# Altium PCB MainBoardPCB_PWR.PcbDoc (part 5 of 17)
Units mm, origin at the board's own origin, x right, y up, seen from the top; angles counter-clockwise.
Board outline 333.63 x 349.38 mm, 16 copper layers (L1, L2 (GND), L3 (Sign), L4 (GND), L5 (Sign), L6 (PWR/GND), L7(PWR/GND), L8 (PWR/GND), L9 (PWR/GND), L10 (PWR/GND), L11 (PWR/GND), L12 (Sign), L13 (GND), L14 (Sign), L15 (GND), L16), stack 2.503 mm thick; 2187 components, 1615 nets, 7987 pads, 1695 vias.
Unrouted connection lines stored in the file: 4757.
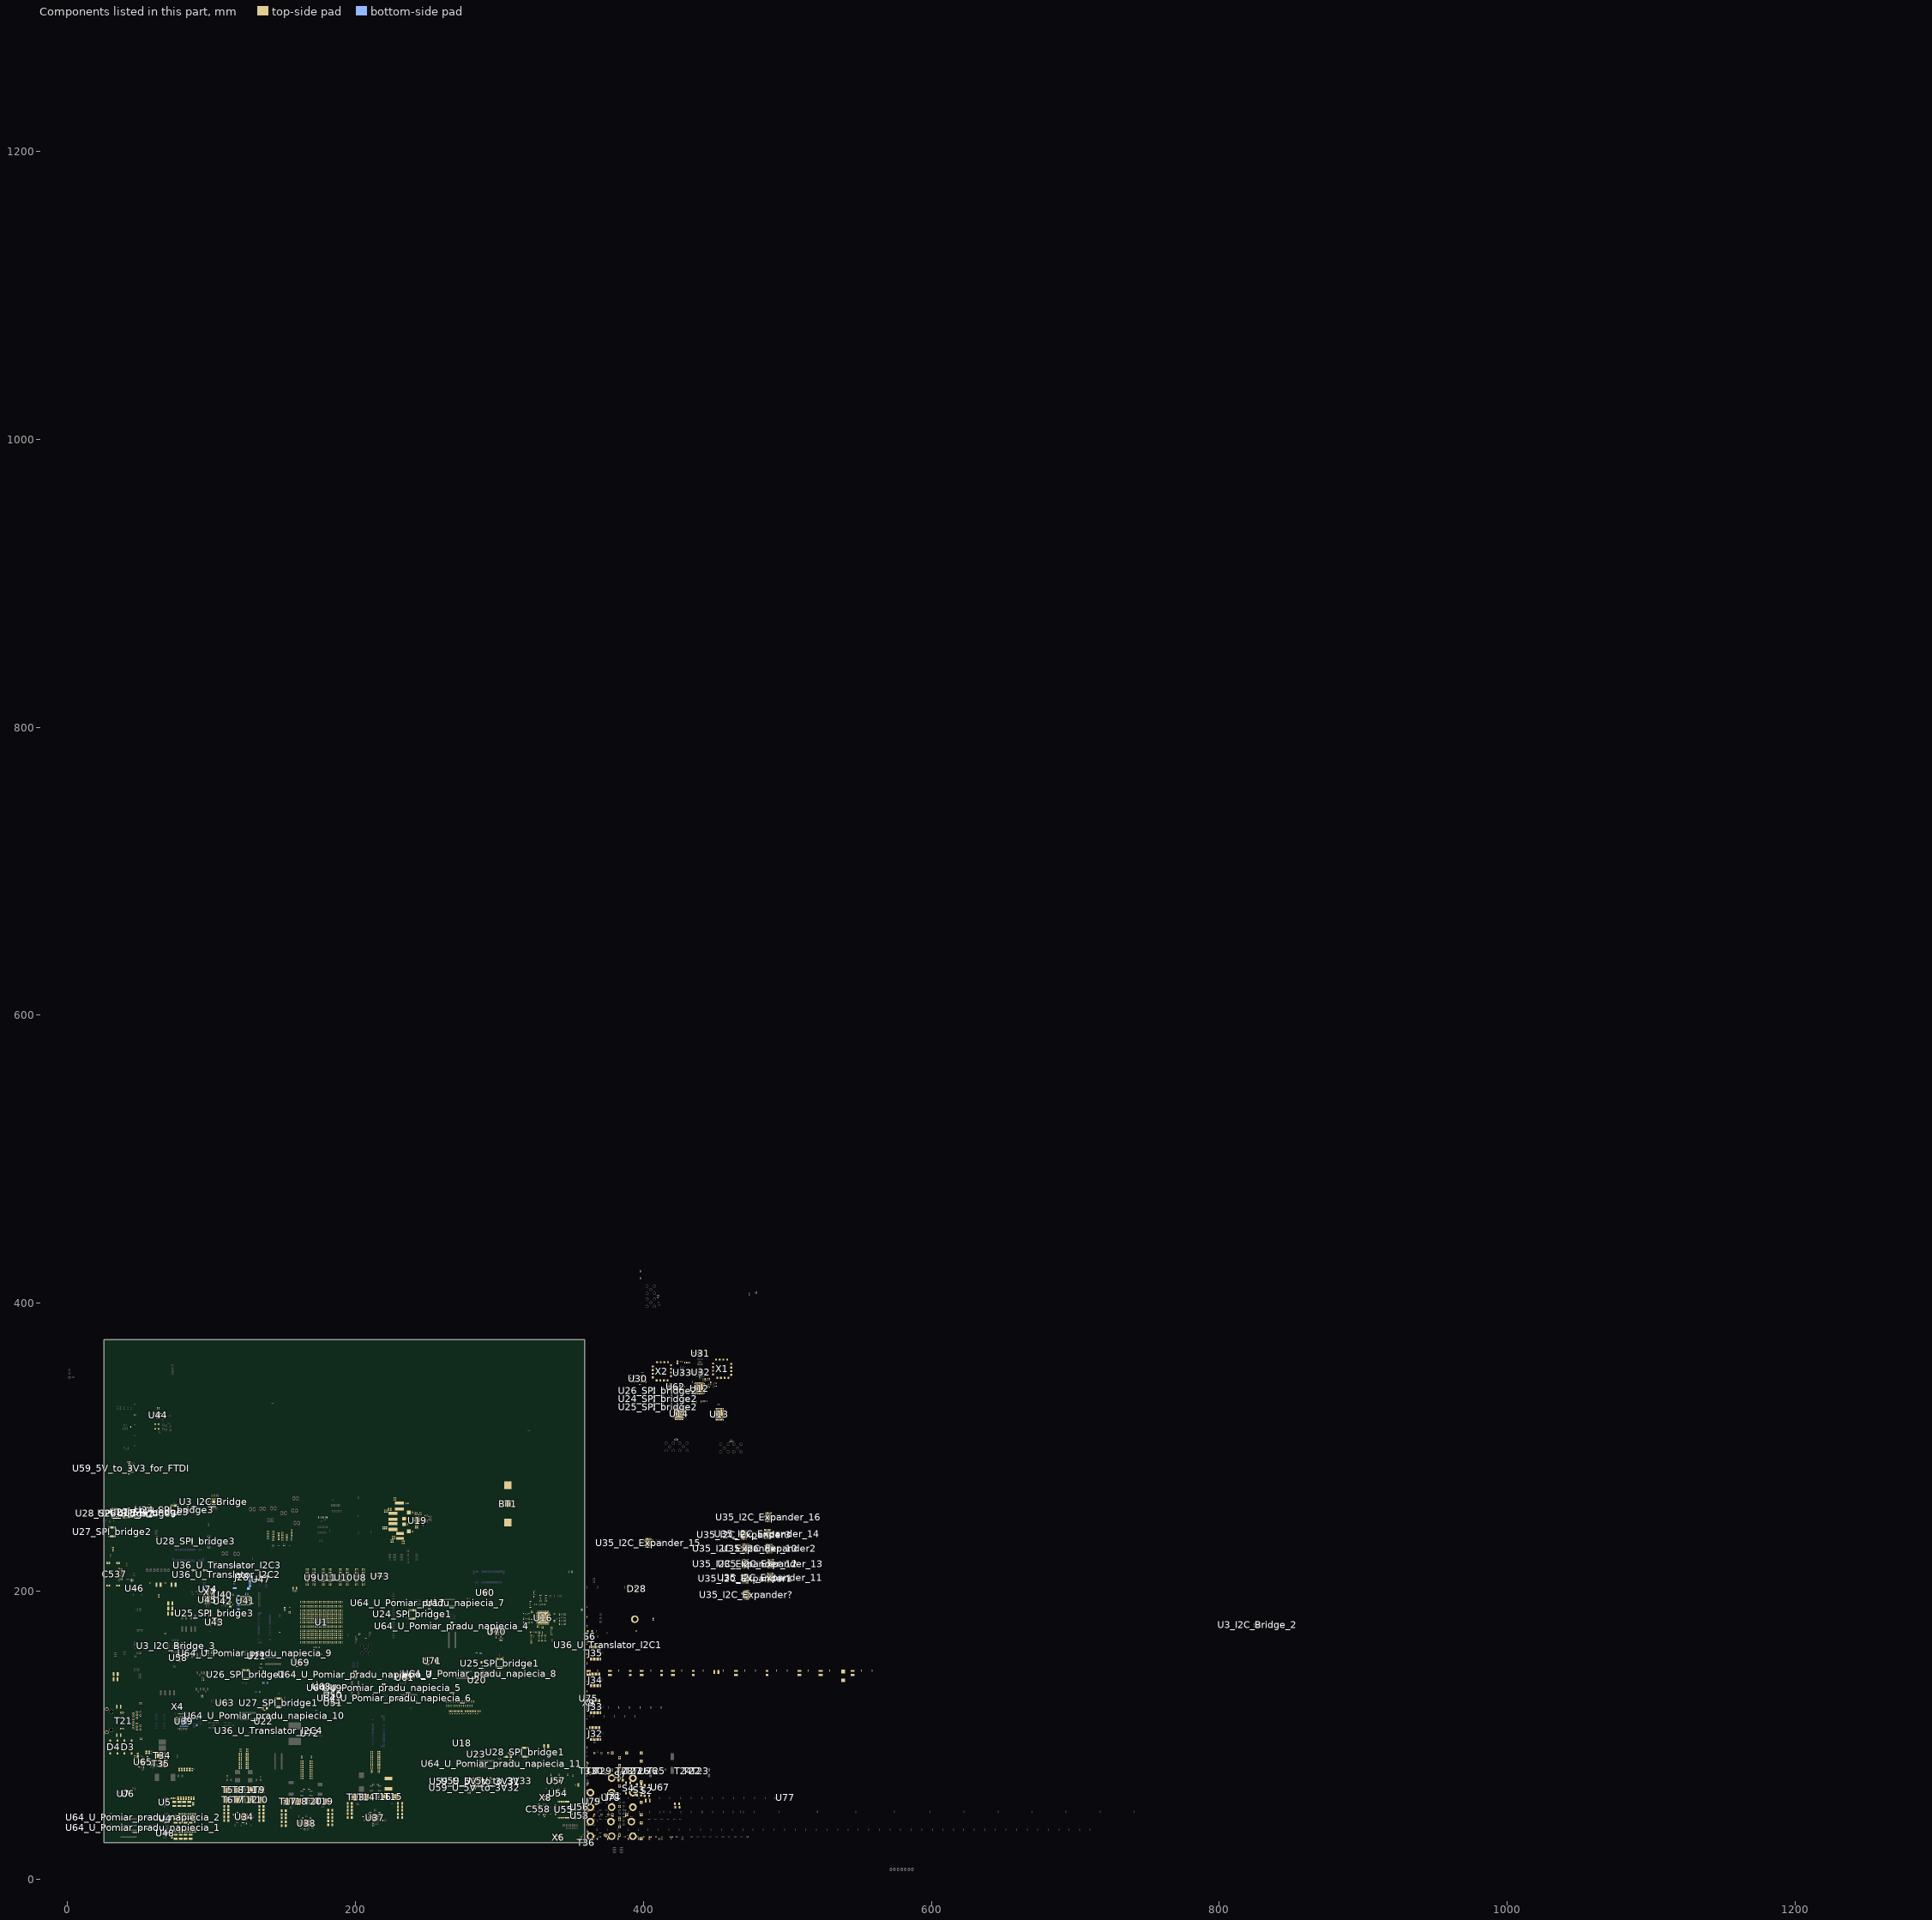
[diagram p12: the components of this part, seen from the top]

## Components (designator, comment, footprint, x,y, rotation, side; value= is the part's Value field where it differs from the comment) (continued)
T21 "7499511440" 7499511440 36.068,109.982 r90 bottom
T22 "IRLML6401TRPBF" IRLML6401PbF 433.807,75.082 r0 top
T23 "IRLML6401TRPBF" IRLML6401PbF 439.661,75.082 r0 top
T24 "SI2342DS-T1-GE3" SI2342DS-T1-GE3 427.952,75.184 r0 top
T25 "SI2342DS-T1-GE3" SI2342DS-T1-GE3 409.27,75.184 r0 top
T26 "SI2342DS-T1-GE3" SI2342DS-T1-GE3 398.882,75.184 r0 top
T27 "IRLML6401TRPBF" IRLML6401PbF 393.027,75.082 r0 top
T28 "SI2342DS-T1-GE3" SI2342DS-T1-GE3 387.172,75.184 r0 top
T29 "SI2342DS-T1-GE3" SI2342DS-T1-GE3 372.224,75.184 r0 top
T30 "IRLML6401TRPBF" IRLML6401PbF 366.37,75.082 r0 top
T31 "SI2342DS-T1-GE3" SI2342DS-T1-GE3 361.899,75.184 r0 top
T34 "RJK0651DPB-00#J5" RJK0651DPB 64.98,85.852 r180 top
T35 "SIJ482DP-T1-GE3" SiJ482DP 65.046,80.055 r0 top
T36 "SI2342DS-T1-GE3" SI2342DS-T1-GE3 360.505,25.232 r0 top
TP1_I2C_Bridge "TestPoint" TestPoint 766.635,73.393 r90 top (schematic designator TP1)
TP1_I2C_Bridge_2 "TestPoint" TestPoint 801.167,176.378 r90 top (schematic designator TP1)
TP1_I2C_Bridge_3 "TestPoint" TestPoint 775.271,83.629 r90 top (schematic designator TP1)
TP2_I2C_Bridge "TestPoint" TestPoint 743.534,73.393 r90 top (schematic designator TP2)
TP2_I2C_Bridge_2 "TestPoint" TestPoint 776.046,176.378 r90 top (schematic designator TP2)
TP2_I2C_Bridge_3 "TestPoint" TestPoint 751.662,83.629 r90 top (schematic designator TP2)
TP3_I2C_Bridge "TestPoint" TestPoint 720.42,73.393 r90 top (schematic designator TP3)
TP3_I2C_Bridge_2 "TestPoint" TestPoint 750.9,176.378 r90 top (schematic designator TP3)
TP3_I2C_Bridge_3 "TestPoint" TestPoint 728.04,83.629 r90 top (schematic designator TP3)
TP4_I2C_Bridge "TestPoint" TestPoint 697.319,73.393 r90 top (schematic designator TP4)
TP4_I2C_Bridge_2 "TestPoint" TestPoint 725.754,176.378 r90 top (schematic designator TP4)
TP4_I2C_Bridge_3 "TestPoint" TestPoint 704.418,83.629 r90 top (schematic designator TP4)
TP5_I2C_Bridge "TestPoint" TestPoint 674.205,73.393 r90 top (schematic designator TP5)
TP5_I2C_Bridge_2 "TestPoint" TestPoint 700.608,176.378 r90 top (schematic designator TP5)
TP5_I2C_Bridge_3 "TestPoint" TestPoint 680.809,83.629 r90 top (schematic designator TP5)
TP6_I2C_Bridge "TestPoint" TestPoint 651.104,73.393 r90 top (schematic designator TP6)
TP6_I2C_Bridge_2 "TestPoint" TestPoint 675.488,176.378 r90 top (schematic designator TP6)
TP6_I2C_Bridge_3 "TestPoint" TestPoint 657.187,83.629 r90 top (schematic designator TP6)
TP7_I2C_Bridge "TestPoint" TestPoint 484.518,73.393 r90 top (schematic designator TP7)
TP7_I2C_Bridge_2 "TestPoint" TestPoint 494.69,176.378 r90 top (schematic designator TP7)
TP7_I2C_Bridge_3 "TestPoint" TestPoint 487.058,83.629 r90 top (schematic designator TP7)
TP8_I2C_Bridge "TestPoint" TestPoint 627.99,73.393 r90 top (schematic designator TP8)
TP8_I2C_Bridge_2 "TestPoint" TestPoint 650.342,176.378 r90 top (schematic designator TP8)
TP8_I2C_Bridge_3 "TestPoint" TestPoint 633.578,83.629 r90 top (schematic designator TP8)
TP9_I2C_Bridge "TestPoint" TestPoint 604.888,73.393 r90 top (schematic designator TP9)
TP9_I2C_Bridge_2 "TestPoint" TestPoint 625.196,176.378 r90 top (schematic designator TP9)
TP9_I2C_Bridge_3 "TestPoint" TestPoint 609.956,83.629 r90 top (schematic designator TP9)
TP10_I2C_Bridge "TestPoint" TestPoint 580.504,73.393 r90 top (schematic designator TP10)
TP10_I2C_Bridge_2 "TestPoint" TestPoint 598.805,176.378 r90 top (schematic designator TP10)
TP10_I2C_Bridge_3 "TestPoint" TestPoint 585.076,83.629 r90 top (schematic designator TP10)
TP11_I2C_Bridge "TestPoint" TestPoint 556.387,73.393 r90 top (schematic designator TP11)
TP11_I2C_Bridge_2 "TestPoint" TestPoint 572.643,176.378 r90 top (schematic designator TP11)
TP11_I2C_Bridge_3 "TestPoint" TestPoint 560.438,83.629 r90 top (schematic designator TP11)
TP12_I2C_Bridge "TestPoint" TestPoint 532.003,73.393 r90 top (schematic designator TP12)
TP12_I2C_Bridge_2 "TestPoint" TestPoint 546.227,176.378 r90 top (schematic designator TP12)
TP12_I2C_Bridge_3 "TestPoint" TestPoint 535.559,83.629 r90 top (schematic designator TP12)
TP13_I2C_Bridge "TestPoint" TestPoint 507.632,73.393 r90 top (schematic designator TP13)
TP13_I2C_Bridge_2 "TestPoint" TestPoint 519.811,176.378 r90 top (schematic designator TP13)
TP13_I2C_Bridge_3 "TestPoint" TestPoint 510.667,83.629 r90 top (schematic designator TP13)
TP14_I2C_Bridge "TestPoint" TestPoint 460.146,73.393 r90 top (schematic designator TP14)
TP14_I2C_Bridge_2 "TestPoint" TestPoint 468.274,176.378 r90 top (schematic designator TP14)
TP14_I2C_Bridge_3 "TestPoint" TestPoint 462.166,83.629 r90 top (schematic designator TP14)
TP15_I2C_Bridge "TestPoint" TestPoint 534.889,26.273 r90 top (schematic designator TP15)
TP15_I2C_Bridge_2 "TestPoint" TestPoint 441.858,176.378 r90 top (schematic designator TP15)
TP15_I2C_Bridge_3 "TestPoint" TestPoint 437.286,83.629 r90 top (schematic designator TP15)
TP16_I2C_Bridge "TestPoint" TestPoint 531.012,27.724 r90 top (schematic designator TP16)
TP16_I2C_Bridge_2 "TestPoint" TestPoint 415.442,176.378 r90 top (schematic designator TP16)
TP16_I2C_Bridge_3 "TestPoint" TestPoint 522.58,112.344 r90 top (schematic designator TP16)
TP17_I2C_Bridge "TestPoint" TestPoint 524.713,29.273 r90 top (schematic designator TP17)
TP17_I2C_Bridge_2 "TestPoint" TestPoint 389.052,176.378 r90 top (schematic designator TP17)
TP17_I2C_Bridge_3 "TestPoint" TestPoint 499.605,110.401 r90 top (schematic designator TP17)
TP18_I2C_Bridge "TestPoint" TestPoint 516.382,26.772 r90 top (schematic designator TP18)
TP18_I2C_Bridge_2 "TestPoint" TestPoint 362.636,176.378 r90 top (schematic designator TP18)
TP18_I2C_Bridge_3 "TestPoint" TestPoint 506.4,116.599 r90 top (schematic designator TP18)
TP19 "TestPoint" TestPoint 371.297,22.606 r0 top
TP20 "TestPoint" TestPoint 365.925,19.431 r0 top
TP21 "TestPoint" TestPoint 544.187,14.173 r0 top
TP22 "TestPoint" TestPoint 536.821,14.173 r0 top
TP23 "TestPoint" TestPoint 529.455,14.173 r0 top
TP24 "TestPoint" TestPoint 522.089,14.173 r0 top
TP25 "TestPoint" TestPoint 514.723,14.173 r0 top
TP26 "TestPoint" TestPoint 507.357,14.173 r0 top
TP27 "TestPoint" TestPoint 500.004,14.173 r0 top
TP28 "TestPoint" TestPoint 492.638,14.173 r0 top
TP29 "TestPoint" TestPoint 485.272,14.173 r0 top
TP30 "TestPoint" TestPoint 477.906,14.173 r0 top
TP31 "TestPoint" TestPoint 470.984,14.173 r0 top
TP32 "TestPoint" TestPoint 463.618,14.173 r0 top
TP33 "TestPoint" TestPoint 456.252,14.173 r0 top
TP34 "TestPoint" TestPoint 448.886,14.173 r0 top
TP35 "TestPoint" TestPoint 441.52,14.173 r0 top
TP36 "TestPoint" TestPoint 434.154,14.173 r0 top
TP37 "TestPoint" TestPoint 426.788,14.173 r0 top
TP38 "TestPoint" TestPoint 419.435,14.173 r0 top
TP39 "TestPoint" TestPoint 412.069,14.173 r0 top
TP40 "TestPoint" TestPoint 404.703,14.173 r0 top
TP41 "TestPoint" TestPoint 397.769,14.173 r0 top
TP42 "TestPoint" TestPoint 506.882,27.546 r0 top
TP43 "TestPoint" TestPoint 528.795,18.11 r0 top
TP44 "TestPoint" TestPoint 521.429,18.11 r0 top
TP45 "TestPoint" TestPoint 514.063,18.11 r0 top
TP46 "TestPoint" TestPoint 506.697,18.11 r0 top
TP47 "TestPoint" TestPoint 499.331,18.11 r0 top
TP48 "TestPoint" TestPoint 491.965,18.11 r0 top
TP49 "TestPoint" TestPoint 484.599,18.11 r0 top
TP50_SPI_bridge1 "TestPoint" TestPoint 510.172,93.866 r90 top (schematic designator TP50)
TP50_SPI_bridge2 "TestPoint" TestPoint 588.645,186.614 r90 top (schematic designator TP50)
TP50_SPI_bridge3 "TestPoint" TestPoint 513.207,104.102 r90 top (schematic designator TP50)
TP51_SPI_bridge1 "TestPoint" TestPoint 485.788,93.866 r90 top (schematic designator TP51)
TP51_SPI_bridge2 "TestPoint" TestPoint 563.753,186.614 r90 top (schematic designator TP51)
TP51_SPI_bridge3 "TestPoint" TestPoint 488.328,104.102 r90 top (schematic designator TP51)
TP52_SPI_bridge1 "TestPoint" TestPoint 461.162,93.866 r90 top (schematic designator TP52)
TP52_SPI_bridge2 "TestPoint" TestPoint 538.607,186.614 r90 top (schematic designator TP52)
TP52_SPI_bridge3 "TestPoint" TestPoint 463.182,104.102 r90 top (schematic designator TP52)
TP53_SPI_bridge1 "TestPoint" TestPoint 436.524,93.866 r90 top (schematic designator TP53)
TP53_SPI_bridge2 "TestPoint" TestPoint 513.461,186.614 r90 top (schematic designator TP53)
TP53_SPI_bridge3 "TestPoint" TestPoint 438.048,104.102 r90 top (schematic designator TP53)
TP54_SPI_bridge1 "TestPoint" TestPoint 411.899,93.866 r90 top (schematic designator TP54)
TP54_SPI_bridge2 "TestPoint" TestPoint 488.34,186.614 r90 top (schematic designator TP54)
TP54_SPI_bridge3 "TestPoint" TestPoint 412.915,104.102 r90 top (schematic designator TP54)
TP55_SPI_bridge1 "TestPoint" TestPoint 387.261,93.866 r90 top (schematic designator TP55)
TP55_SPI_bridge2 "TestPoint" TestPoint 463.194,186.614 r90 top (schematic designator TP55)
TP55_SPI_bridge3 "TestPoint" TestPoint 387.769,104.102 r90 top (schematic designator TP55)
TP56_SPI_bridge1 "TestPoint" TestPoint 362.636,93.866 r90 top (schematic designator TP56)
TP56_SPI_bridge2 "TestPoint" TestPoint 438.048,186.614 r90 top (schematic designator TP56)
TP56_SPI_bridge3 "TestPoint" TestPoint 365.484,103.796 r90 top (schematic designator TP56)
TP57_SPI_bridge1 "TestPoint" TestPoint 411.988,95.25 r90 top (schematic designator TP57)
TP57_SPI_bridge2 "TestPoint" TestPoint 412.928,186.614 r90 top (schematic designator TP57)
TP57_SPI_bridge3 "TestPoint" TestPoint 413.004,105.664 r90 top (schematic designator TP57)
TP58_SPI_bridge1 "TestPoint" TestPoint 387.35,95.25 r90 top (schematic designator TP58)
TP58_SPI_bridge2 "TestPoint" TestPoint 387.782,186.614 r90 top (schematic designator TP58)
TP58_SPI_bridge3 "TestPoint" TestPoint 387.858,105.664 r90 top (schematic designator TP58)
TP59_SPI_bridge1 "TestPoint" TestPoint 362.712,95.25 r90 top (schematic designator TP59)
TP59_SPI_bridge2 "TestPoint" TestPoint 362.636,186.614 r90 top (schematic designator TP59)
TP59_SPI_bridge3 "TestPoint" TestPoint 362.712,105.664 r90 top (schematic designator TP59)
TP60_U_Translator_I2C1 "TestPoint" TestPoint 395.91,196.85 r90 top (schematic designator TP60)
TP60_U_Translator_I2C2 "TestPoint" TestPoint 396.405,114.338 r90 top (schematic designator TP60)
TP60_U_Translator_I2C3 "TestPoint" TestPoint 1269.987,1269.987 r0 top (schematic designator TP60)
TP60_U_Translator_I2C4 "TestPoint" TestPoint 1269.987,1269.987 r0 top (schematic designator TP60)
TP61_U_Translator_I2C1 "TestPoint" TestPoint 362.636,196.85 r90 top (schematic designator TP61)
TP61_U_Translator_I2C2 "TestPoint" TestPoint 362.636,114.338 r90 top (schematic designator TP61)
TP61_U_Translator_I2C3 "TestPoint" TestPoint 1269.987,1269.987 r0 top (schematic designator TP61)
TP61_U_Translator_I2C4 "TestPoint" TestPoint 1269.987,1269.987 r0 top (schematic designator TP61)
TP62 "TestPoint" TestPoint 553.733,37.998 r0 top
TP63 "TestPoint" TestPoint 546.367,37.998 r0 top
TP64 "TestPoint" TestPoint 539.001,37.998 r0 top
TP65 "TestPoint" TestPoint 531.635,37.998 r0 top
TP66 "TestPoint" TestPoint 524.281,37.998 r0 top
TP67 "TestPoint" TestPoint 516.915,37.998 r0 top
TP68 "TestPoint" TestPoint 509.549,37.998 r0 top
TP69 "TestPoint" TestPoint 502.183,37.998 r0 top
TP70 "TestPoint" TestPoint 494.817,37.998 r0 top
TP71 "TestPoint" TestPoint 487.896,37.998 r0 top
TP72 "TestPoint" TestPoint 480.53,37.998 r0 top
TP73 "TestPoint" TestPoint 473.164,37.998 r0 top
TP74 "TestPoint" TestPoint 465.798,37.998 r0 top
TP75 "TestPoint" TestPoint 458.432,29.273 r0 top
TP76 "TestPoint" TestPoint 451.066,29.273 r0 top
TP77 "TestPoint" TestPoint 443.713,29.273 r0 top
TP78 "TestPoint" TestPoint 436.347,29.273 r0 top
TP79 "TestPoint" TestPoint 428.981,29.273 r0 top
TP80 "TestPoint" TestPoint 421.615,29.273 r0 top
TP81 "TestPoint" TestPoint 414.693,29.273 r0 top
TP82 "TestPoint" TestPoint 407.327,29.273 r0 top
TP83 "TestPoint" TestPoint 399.961,29.273 r0 top
TP84 "TestPoint" TestPoint 392.595,29.273 r0 top
TP85 "TestPoint" TestPoint 385.229,29.273 r0 top
TP86 "TestPoint" TestPoint 377.863,29.273 r0 top
TP87 "TestPoint" TestPoint 370.497,29.273 r0 top
TP88 "TestPoint" TestPoint 363.131,29.273 r0 top
TP91 "TestPoint" TestPoint 498.515,27.445 r0 top
TP92 "TestPoint" TestPoint 491.149,27.445 r0 top
U1 "FBVB900" "FBVB900 XX" 176.427,178.427 r90 top locked
U3_I2C_Bridge "TCA9548" TCA9548 101.6,262.001 r90 top (schematic designator U3)
U3_I2C_Bridge_2 "TCA9548" TCA9548 826.389,176.581 r90 top (schematic designator U3)
U3_I2C_Bridge_3 "TCA9548" TCA9548 75.299,161.955 r90 top (schematic designator U3)
U4 "TPS2121RUXT" TPS212x 67.81,42 r180 top
U5 "TPS2121RUXT" TPS212x 67.629,53.445 r180 top
U6 "FPF2895CUCX" FPF2895C-D 41.961,59.258 r0 top
U7 "FPF2895CUCX" FPF2895C-D 38.684,59.233 r0 top
U8 "MT40A512M16JY" MT40A512M16JY 203.187,209.448 r180 top locked
U9 "MT40A512M16JY" MT40A512M16JY 168.806,209.448 r180 top locked
U10 "MT40A512M16JY" MT40A512M16JY 191.727,209.448 r180 top locked
U11 "MT40A512M16JY" MT40A512M16JY 180.266,209.448 r180 top locked
U12 "LTC6952" LTC6952 438.868,340.842 r0 top
U13 "LTC6952" LTC6952 452.78,322.838 r0 top
U14 "LTC6952" LTC6952 424.713,323.088 r0 top
U15 "SN74AXC4T774PWR" SN74AXC4T774PWR 40.825,254.381 r90 top
U16 "LMK05028" LMK05028 330.203,181.514 r90 top
U17 "FPF2895CUCX" FPF2895C-D 255.855,191.833 r0 top
U18 "FPF2895CUCX" FPF2895C-D 274.044,94.567 r0 top
U19 "LT3504EUFD#PBF" LT3504 242.974,249.058 r0 top
U20 "FPF2895CUCX" FPF2895C-D 284.534,138.207 r270 top
U21 "FPF2895CUCX" FPF2895C-D 131.372,155.013 r270 top
U22 "FPF2895CUCX" FPF2895C-D 136.183,109.693 r90 top
U23 "FPF2895CUCX" FPF2895C-D 283.885,86.756 r0 top
U24_SPI_bridge1 "SN74AXC4T774PWR" SN74AXC4T774PWR 239.507,183.991 r270 top (schematic designator U24)
U24_SPI_bridge2 "SN74AXC4T774PWR" SN74AXC4T774PWR 410.235,333.565 r0 bottom (schematic designator U24)
U24_SPI_bridge3 "SN74AXC4T774PWR" SN74AXC4T774PWR 74.295,256.413 r90 top (schematic designator U24)
U25_SPI_bridge1 "SN74AXC4T774PWR" SN74AXC4T774PWR 300.217,149.945 r90 top (schematic designator U25)
U25_SPI_bridge2 "SN74AXC4T774PWR" SN74AXC4T774PWR 410.235,327.914 r0 bottom (schematic designator U25)
U25_SPI_bridge3 "SN74AXC4T774PWR" SN74AXC4T774PWR 101.854,184.658 r180 top (schematic designator U25)
U26_SPI_bridge1 "SN74AXC4T774PWR" SN74AXC4T774PWR 123.922,142.113 r270 top (schematic designator U26)
U26_SPI_bridge2 "SN74AXC4T774PWR" SN74AXC4T774PWR 410.235,339.217 r0 bottom (schematic designator U26)
U26_SPI_bridge3 "SN74AXC4T774PWR" SN74AXC4T774PWR 48.514,254.127 r90 top (schematic designator U26)
U27_SPI_bridge1 "SN74AXC4T774PWR" SN74AXC4T774PWR 146.685,122.555 r90 top (schematic designator U27)
U27_SPI_bridge2 "SN74AXC4T774PWR" SN74AXC4T774PWR 30.872,241.3 r90 top (schematic designator U27)
U27_SPI_bridge3 "SN74AXC4T774PWR" SN74AXC4T774PWR 56.896,254.889 r90 top (schematic designator U27)
U28_SPI_bridge1 "SN74AXC4T774PWR" SN74AXC4T774PWR 317.703,88.138 r270 top (schematic designator U28)
U28_SPI_bridge2 "SN74AXC4T774PWR" SN74AXC4T774PWR 33.147,254.127 r90 top (schematic designator U28)
U28_SPI_bridge3 "SN74AXC4T774PWR" SN74AXC4T774PWR 89.154,234.823 r180 top (schematic designator U28)
U30 "DAC1220" DAC1220 396.138,347.599 r0 top
U31 "SI53323-B-GM" SI53323-B-GM 439.675,365.129 r270 top
U32 "SI53323-B-GM" SI53323-B-GM 439.786,351.917 r270 top
U33 "CDCM1802RGTT" CDCM1802RGTT 427.002,351.786 r0 top
U34 "ADP1850ACPZ-R7" ADP1850 122.727,43.156 r90 top
U35_I2C_Expander1 "MCP23017-E/ML" QFN-ML28_N 470.886,208.717 r90 top (schematic designator U35)
U35_I2C_Expander2 "MCP23017-E/ML" QFN-ML28_N 487.165,229.565 r90 top (schematic designator U35)
U35_I2C_Expander3 "MCP23017-E/ML" QFN-ML28_N 469.845,239.27 r90 top (schematic designator U35)
U35_I2C_Expander? "MCP23017-E/ML" QFN-ML28_N 471.545,197.546 r90 top (schematic designator U35)
U35_I2C_Expander_10 "MCP23017-E/ML" QFN-ML28_N 470.77,229.715 r90 top (schematic designator U35)
U35_I2C_Expander_11 "MCP23017-E/ML" QFN-ML28_N 488.129,209.461 r90 top (schematic designator U35)
U35_I2C_Expander_12 "MCP23017-E/ML" QFN-ML28_N 470.77,219.05 r90 top (schematic designator U35)
U35_I2C_Expander_13 "MCP23017-E/ML" QFN-ML28_N 488.417,219.05 r90 top (schematic designator U35)
U35_I2C_Expander_14 "MCP23017-E/ML" QFN-ML28_N 486.067,239.647 r90 top (schematic designator U35)
U35_I2C_Expander_15 "MCP23017-E/ML" QFN-ML28_N 403.454,233.52 r90 top (schematic designator U35)
U35_I2C_Expander_16 "MCP23017-E/ML" QFN-ML28_N 486.853,251.489 r90 top (schematic designator U35)
U36_U_Translator_I2C1 "PCA9306" PCA9306 375.158,162.56 r90 top (schematic designator U36)
U36_U_Translator_I2C2 "PCA9306" PCA9306 110.157,211.329 r0 top (schematic designator U36)
U36_U_Translator_I2C3 "PCA9306" PCA9306 110.744,218.059 r90 top (schematic designator U36)
U36_U_Translator_I2C4 "PCA9306" PCA9306 139.618,103.129 r90 top (schematic designator U36)
U37 "ADP1850ACPZ-R7" ADP1850 213.545,42.609 r90 top
U38 "ADP1850ACPZ-R7" ADP1850 166.033,38.765 r90 top
U39 "DP83867ERGZT" DP83867E 80.772,109.474 r0 bottom
U40 "MCP1727T-ADJE/MF" MCP1727T-ADJE/MF 107.816,197.335 r0 top
U41 "MTFC8GAKAJCN-4MITTR" "MTFC8GAKAJCN-4M IT TR" 123.718,193.229 r270 top locked
U42 "MCP1727T-ADJE/MF" MCP1727T-ADJE/MF 107.817,193.048 r0 top
U43 "SN74AXC4T774PWR" SN74AXC4T774PWR 101.854,178.435 r180 top
U44 "MAX16025TE+T" MAX16025TE+T 62.95,322.241 r0 top
U45 "USB3320C-EZK-TR" USB3320 97.028,193.802 r0 top
U46 "FPF2895CUCX" FPF2895C-D 46.377,201.889 r0 top
U47 "IP4856CX25/CZ" IP4856CX25/C 134.239,208.153 r180 bottom
U48 "TPS2121RUXT" TPS212x 68.017,31.762 r180 top
U49 "MCP1727T-ADJE/MF" MCP1727T-ADJE/MF 184.259,132.634 r0 top
U50 "MCP1727T-ADJE/MF" MCP1727T-ADJE/MF 184.259,127.785 r0 top
U51 "MCP1727T-ADJE/MF" MCP1727T-ADJE/MF 184.259,122.538 r0 top
U53 "SN74AXC4T774PWR" SN74AXC4T774PWR 355.571,44.092 r0 top
U54 "93LC56BT-I/OT" 93LC56BT 340.792,59.45 r0 top
U55 "FT4232HL-REEL" FT4232HL 344.513,48.151 r0 top
U56 "SN74AXC4T774PWR" SN74AXC4T774PWR 355.571,50.05 r0 top
U57 "SN74AXC4T774PWR" SN74AXC4T774PWR 339.141,68.086 r0 top
U58 "ISM330DHCXTR" ISM330DHCXL 76.835,153.631 r0 top
U59_5V_to_3V3_for_FTDI "MCP1727T-ADJE/MF" MCP1727T-ADJE/MF 44.076,285.34 r90 top (schematic designator U59)
U59_U_5V_to_3V31 "MCP1727T-ADJE/MF" MCP1727T-ADJE/MF 282.997,67.984 r180 top (schematic designator U59)
U59_U_5V_to_3V32 "MCP1727T-ADJE/MF" MCP1727T-ADJE/MF 282.754,63.534 r180 top (schematic designator U59)
U59_U_5V_to_3V33 "MCP1727T-ADJE/MF" MCP1727T-ADJE/MF 290.931,68.309 r0 top (schematic designator U59)
U60 "ADP1741ACPZ-R7" ADP1752_1753/ADP1740_1741 290.04,199.031 r0 top
U61 "TPS7A8801RTJT" TPS7A88 234.192,140.005 r180 top
U62 "LT3042EDD#PBF" LT3042 422.33,341.842 r0 top
U63 "MAX3051EKA+T" "MAX3051EKA+T SOT23" 109.213,122.453 r180 top
U64_U_Pomiar_pradu_napiecia_1 "INA226AIDGSR" INA226 52.476,35.768 r180 top (schematic designator U64)
U64_U_Pomiar_pradu_napiecia_2 "INA226AIDGSR" INA226 52.476,42.783 r180 top (schematic designator U64)
U64_U_Pomiar_pradu_napiecia_3 "INA226AIDGSR" INA226 199.796,142.062 r270 top (schematic designator U64)
U64_U_Pomiar_pradu_napiecia_4 "INA226AIDGSR" INA226 267.005,175.819 r270 top (schematic designator U64)
U64_U_Pomiar_pradu_napiecia_5 "INA226AIDGSR" INA226 219.753,132.97 r270 top (schematic designator U64)
U64_U_Pomiar_pradu_napiecia_6 "INA226AIDGSR" INA226 226.98,125.705 r0 top (schematic designator U64)
U64_U_Pomiar_pradu_napiecia_7 "INA226AIDGSR" INA226 250.29,191.829 r0 top (schematic designator U64)
U64_U_Pomiar_pradu_napiecia_8 "INA226AIDGSR" INA226 286.131,142.579 r180 top (schematic designator U64)
U64_U_Pomiar_pradu_napiecia_9 "INA226AIDGSR" INA226 130.14,157.039 r0 top (schematic designator U64)
U64_U_Pomiar_pradu_napiecia_10 "INA226AIDGSR" INA226 136.738,113.546 r180 top (schematic designator U64)
U64_U_Pomiar_pradu_napiecia_11 "INA226AIDGSR" INA226 301.502,79.993 r180 top (schematic designator U64)
U65 "MAX17557ATP+" MAX17557 52.332,81.207 r0 top
U67 "LM3880MFE-1AF/NOPB" LM3880-Q1 411.501,63.767 r0 top
U68 "LM3880MFE-1AF/NOPB" LM3880-Q1 176.716,133.859 r0 top
U69 "ADP1741ACPZ-R7" ADP1752_1753/ADP1740_1741 161.718,150.462 r180 top
U70 "TPS7A8801RTJT" TPS7A88 298.259,171.723 r0 top
U71 "UA78M08CDCYR" UA78M 253.164,151.682 r0 top
U72 "INA226AIDGSR" INA226 168.231,101.245 r180 top
U73 "ST1L08SPUR" ST1L08 217.151,210.383 r0 top
U74 "SN74LVC1G08DBVR" SN74LVC1G08DBVR 97.278,201.381 r270 bottom
U75 "ESDCAN02-2BWY" ESDCAN02-2BWY 361.798,125.425 r0 top
U76 "SN74LVC1G08DBVR" SN74LVC1G08DBVR 403.758,75.057 r0 top
U77 "NC7WZ07FHX" NC7WZ07FHX 498.602,56.591 r90 top
U78 "NC7WZ07FHX" NC7WZ07FHX 377.215,56.591 r90 top
U79 "SN74AXC4T774PWR" SN74AXC4T774PWR 364.058,54.026 r0 top
X1 "OSC CRO 2000-2000 MHZ SMD .5X.5" CVCO55CW 448.335,360.807 r270 top
X2 "OSC VCO 490-540MHZ SMD .5X.5\"" CVCO55CW 406.552,346.329 r0 top
X3 "2.4576MHz" Crystal 397.946,417.268 r90 top
X4 "FA-23825.0000MB-C3" FA-23825.0000MB-C3 76.532,119.611 r270 bottom
X5 "32.768kHz" FC-135R/FC-135 157.874,202.222 r0 top
X6 "510CCA50M0000BAG" Si510 340.873,28.842 r0 top
X7 "TSX-322524.0000MF15X-AC6" "TSX-3225 24.0000MF15X-AC6" 98.778,199.171 r0 top
X8 "ECS-120-8-33-RWY-TR" ECS-120-8-33-RWY-TR 332.156,56.529 r0 top
X9 "SIT1602BI-12-33E-48.000000G" SiT1602B 362.115,122.364 r0 top

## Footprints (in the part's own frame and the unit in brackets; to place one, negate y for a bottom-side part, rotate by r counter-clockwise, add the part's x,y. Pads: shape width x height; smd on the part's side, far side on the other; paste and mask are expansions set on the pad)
93LC56BT [mm] "SOT-23-6, 6-Leads, Body 2,90x1,55mm, Pitch 0,95mm, IPC High Density"
  rect 1.1x0.6 smd: 1(-1.4,0.95) 2(-1.4,0) 3(-1.4,-0.95) 4(1.4,-0.95) 5(1.4,0) 6(1.4,0.95)
  silkscreen extent -1.52,-1.55 0.5,1.92, body extent -1.35,-1.55 1.35,1.55, height 1.45
2007132 [mm] "SFP Connector"
  rect 2x2 hole 1.05: SH1(-2.5,-5) SH1(0,0) SH2(8.575,-5) SH3(14.25,-5) SH4(0,10) SH5(5.675,10) SH6(11.075,10) SH7(14.25,15) SH8(0,20) SH9(0,30) SH10(14.25,5) SH13(19.925,10) SH14(25.325,10) SH17(22.825,-5) SH20(34.175,10) SH21(39.575,10) SH22(42.75,10) SH23(42.75,0) SH24(37.075,-5) SH25(42.75,20) SH26(42.75,30) SH29(57,15) SH30(57,5) SH31(57,-5) SH32(48.425,10) SH33(53.825,10) SH34(51.325,-5)
  round 1.458 hole 0.95: SH11(14.25,22.5) SH12(14.25,27.5) SH15(28.5,10) SH16(28.5,0) SH18(28.5,20) SH19(28.5,30) SH27(57,27.5) SH28(57,22.5) SH35(0,17.8) SH36(2.325,32.1) SH37(7.125,32.1) SH38(14.25,17.8) SH39(16.575,32.1) SH40(21.375,32.1) SH41(30.825,32.1) SH42(35.625,32.1) SH43(45.075,32.1) SH44(49.875,32.1) SH45(42.75,17.8) SH46(57,17.8)
  Keep-Out Layer region: 39.745,32.8 45.81,32.8 45.81,31.844 39.745,31.844
  Keep-Out Layer region: 25.485,32.8 31.56,32.8 31.56,31.857 25.485,31.857
  Keep-Out Layer region: 11.205,32.8 17.31,32.8 17.31,31.843 11.205,31.843
  Keep-Out Layer region: 53.789,32.8 58,32.8 58,31.855 53.789,31.855
  Keep-Out Layer region: -1,32.8 3.305,32.8 3.305,31.812 -1,31.812
  Keep-Out Layer region: 56.056,31.8 58,31.8 58,17.317 56.056,17.317
  Keep-Out Layer region: -1.002,31.8 1,31.8 1,17.328 -1.002,17.328
  Keep-Out Layer region: 41.815,31.8 43.75,31.8 43.75,17.327 41.815,17.327
  Keep-Out Layer region: 27.554,31.8 29.5,31.8 29.5,17.334 27.554,17.334
  Keep-Out Layer region: 13.269,31.8 15.25,31.8 15.25,17.324 13.269,17.324
  Keep-Out Layer region: -1.002,17.3 58,17.3 58,-9.517 -1.002,-9.517
  Keep-Out Layer region: 39.72,32.8 45.81,32.8 45.81,31.824 39.72,31.824
  Keep-Out Layer region: 25.472,32.8 31.56,32.8 31.56,31.84 25.472,31.84
  Keep-Out Layer region: 11.207,32.8 17.31,32.8 17.31,31.849 11.207,31.849
  Keep-Out Layer region: 53.775,32.8 58,32.8 58,31.848 53.775,31.848
  Keep-Out Layer region: -1.001,32.8 3.305,32.8 3.305,31.833 -1.001,31.833
  Keep-Out Layer region: 56.018,31.8 58,31.8 58,17.305 56.018,17.305
  Keep-Out Layer region: -1.002,31.8 1,31.8 1,17.334 -1.002,17.334
  Keep-Out Layer region: 41.817,31.8 43.75,31.8 43.75,17.328 41.817,17.328
  Keep-Out Layer region: 27.544,31.8 29.5,31.8 29.5,17.328 27.544,17.328
  Keep-Out Layer region: 13.255,31.8 15.25,31.8 15.25,17.306 13.255,17.306
  Keep-Out Layer region: -1.001,17.3 58,17.3 58,-9.514 -1.001,-9.514
  Keep-Out Layer region: 39.745,32.8 45.81,32.8 45.81,31.844 39.745,31.844
  Keep-Out Layer region: 25.485,32.8 31.56,32.8 31.56,31.857 25.485,31.857
  Keep-Out Layer region: 11.205,32.8 17.31,32.8 17.31,31.843 11.205,31.843
  Keep-Out Layer region: 53.789,32.8 58,32.8 58,31.855 53.789,31.855
  Keep-Out Layer region: -1,32.8 3.305,32.8 3.305,31.812 -1,31.812
  Keep-Out Layer region: 56.056,31.8 58,31.8 58,17.317 56.056,17.317
  Keep-Out Layer region: -1.002,31.8 1,31.8 1,17.328 -1.002,17.328
  Keep-Out Layer region: 41.815,31.8 43.75,31.8 43.75,17.327 41.815,17.327
  Keep-Out Layer region: 27.554,31.8 29.5,31.8 29.5,17.334 27.554,17.334
  Keep-Out Layer region: 13.269,31.8 15.25,31.8 15.25,17.324 13.269,17.324
  Keep-Out Layer region: -1.002,17.3 58,17.3 58,-9.517 -1.002,-9.517
  Keep-Out Layer region: 39.72,32.8 45.81,32.8 45.81,31.824 39.72,31.824
  Keep-Out Layer region: 25.472,32.8 31.56,32.8 31.56,31.84 25.472,31.84
  Keep-Out Layer region: 11.207,32.8 17.31,32.8 17.31,31.849 11.207,31.849
  Keep-Out Layer region: 53.775,32.8 58,32.8 58,31.848 53.775,31.848
  Keep-Out Layer region: -1.001,32.8 3.305,32.8 3.305,31.833 -1.001,31.833
  Keep-Out Layer region: 56.018,31.8 58,31.8 58,17.305 56.018,17.305
  Keep-Out Layer region: -1.002,31.8 1,31.8 1,17.334 -1.002,17.334
  Keep-Out Layer region: 41.817,31.8 43.75,31.8 43.75,17.328 41.817,17.328
  Keep-Out Layer region: 27.544,31.8 29.5,31.8 29.5,17.328 27.544,17.328
  Keep-Out Layer region: 13.255,31.8 15.25,31.8 15.25,17.306 13.255,17.306
  Keep-Out Layer region: -1.001,17.3 58,17.3 58,-9.514 -1.001,-9.514
  Keep-Out Layer region: 39.745,32.8 45.81,32.8 45.81,31.844 39.745,31.844
  Keep-Out Layer region: 25.485,32.8 31.56,32.8 31.56,31.857 25.485,31.857
  Keep-Out Layer region: 11.205,32.8 17.31,32.8 17.31,31.843 11.205,31.843
  Keep-Out Layer region: 53.789,32.8 58,32.8 58,31.855 53.789,31.855
  Keep-Out Layer region: -1,32.8 3.305,32.8 3.305,31.812 -1,31.812
  Keep-Out Layer region: 56.056,31.8 58,31.8 58,17.317 56.056,17.317
  Keep-Out Layer region: -1.002,31.8 1,31.8 1,17.328 -1.002,17.328
  Keep-Out Layer region: 41.815,31.8 43.75,31.8 43.75,17.327 41.815,17.327
  Keep-Out Layer region: 27.554,31.8 29.5,31.8 29.5,17.334 27.554,17.334
  Keep-Out Layer region: 13.269,31.8 15.25,31.8 15.25,17.324 13.269,17.324
  Keep-Out Layer region: -1.002,17.3 58,17.3 58,-9.517 -1.002,-9.517
  Keep-Out Layer region: 39.72,32.8 45.81,32.8 45.81,31.824 39.72,31.824
  Keep-Out Layer region: 25.472,32.8 31.56,32.8 31.56,31.84 25.472,31.84
  Keep-Out Layer region: 11.207,32.8 17.31,32.8 17.31,31.849 11.207,31.849
  Keep-Out Layer region: 53.775,32.8 58,32.8 58,31.848 53.775,31.848
  Keep-Out Layer region: -1.001,32.8 3.305,32.8 3.305,31.833 -1.001,31.833
  Keep-Out Layer region: 56.018,31.8 58,31.8 58,17.305 56.018,17.305
  Keep-Out Layer region: -1.002,31.8 1,31.8 1,17.334 -1.002,17.334
  Keep-Out Layer region: 41.817,31.8 43.75,31.8 43.75,17.328 41.817,17.328
  Keep-Out Layer region: 27.544,31.8 29.5,31.8 29.5,17.328 27.544,17.328
  Keep-Out Layer region: 13.255,31.8 15.25,31.8 15.25,17.306 13.255,17.306
  Keep-Out Layer region: -1.001,17.3 58,17.3 58,-9.514 -1.001,-9.514
  silkscreen extent 0,-9.5 57.25,32.57, body extent -0.97,-16.49 58.08,32.49, height 10.62
79523141 [mm] "Battery Holder, Battery Type: 2016,2020,2025,2032"
  rect 5.2x5.2 smd: 1(-12.95,0) 1(12.95,0)
  rect 4x4 smd: 2(0,0)
  silkscreen extent -10.55,-10.5 10.55,9.3, body extent -15.25,-10.5 15.25,9.3, height 4
1703820001 [mm] "20 Position zSFP+ Receptacle Connector Solder Surface Mount, Right Angle"
  rect 0.5x2 smd: 1(1.4,-4.1) 2(2.2,-4.1) 3(3,-4.1) 4(3.8,-4.1) 5(4.6,-4.1) 6(5.4,-4.1) 7(6.2,-4.1) 8(7,-4.1) 9(7.8,-4.1) 10(8.6,-4.1) 11(8.2,4.1) 12(7.4,4.1) 13(6.6,4.1) 14(5.8,4.1) 15(5,4.1) 16(4.2,4.1) 17(3.4,4.1) 18(2.6,4.1) 19(1.8,4.1) 20(1,4.1)
  round 1.55 hole 1.55: ""(0,0)
  round 1.55 hole 1.55 unplated: ""(9.6,0)
  silkscreen extent -1.33,-8.3 10.92,6.2, body extent -0.69,-4.41 10.31,4.26, height 5.17
7499511440 [mm] "LAN Transformer, body 33.02x17mm"
  rect 1.4x1.4 hole 0.89: 1(5.075,9.63)
  round 1.4 hole 0.89: 2(3.045,9.63) 3(1.015,9.63) 4(-1.015,9.63) 5(-3.045,9.63) 6(-5.075,9.63) 7(6.09,12.17) 8(4.06,12.17) 9(2.03,12.17) 10(-2.03,12.17) 11(-4.06,12.17) 12(-6.09,12.17)
  oval 1.4x1.25 hole 0.89: 13(5.59,2.51) 14(-5.59,2.51) 15(5.59,1.05) 16(-5.59,1.05)
  round 1.52 hole 1.02: 17(6.095,14.71) 18(3.555,14.71) 19(-3.555,14.71) 20(-6.095,14.71)
  round 2.8 hole 2.8 unplated: MH1(-6.35,-5.61) MH2(6.35,-5.61)
  round 2.4 hole 1.57: S1(-8.065,-8.79) S2(8.065,-8.79)
  silkscreen extent -10.72,-16.51 10.72,16.51, body extent -10.8,-16.51 10.8,16.51, height 16.21
9774025243 [mm] "SMT Steel Spacer with internal Thread M2, height 2.5mm"
  round 5.3 / inner round 0 / far side round 0 hole 3 unplated: 1(0,0)
  body extent -2.17,-2.17 2.18,2.17, height 2.5
430181038816 [mm] "Tact Switch, SMD, body 4.5x4.5mm"
  rect 2x1.4 smd: 1(-3.5,1.5) 2(3.5,1.5) 3(-3.5,-1.5) 4(3.5,-1.5)
  silkscreen extent -2.25,-2.25 2.25,2.25, body extent -3.75,-2.25 3.75,2.25, height 3.8
614105150721 [mm] "WR-COM_USB_Micro Type B_Vertical_THT Micro Type B Vertical THT"
  round 0.94 hole 0.44: 1(-1.3,0) 2(-0.65,-1) 3(0,0) 4(0.65,-1) 5(1.3,0)
  oval 0.85x1.5 hole 0.35 slot 1 at 90 deg: Z1(-3.575,-0.22) Z2(3.575,-0.22)
  silkscreen extent -3.7,-1.3 3.7,1.05, body extent -3.99,-1.57 4.01,1.33, height 5.62
692121130100 [mm] "Receptacle TH Reverse Offset 0.14mm"
  rect 1.2x1.2 hole 0.7: 1(-4.35,2.43)
  round 1.2 hole 0.7: 2(-6.85,2.43) 3(-8.85,2.43) 4(-11.35,2.43) 5(-11.85,0.93) 6(-9.85,0.93) 7(-7.85,0.93) 8(-5.85,0.93) 9(-3.85,0.93)
  oval 1.4x2.8 hole 0.8 slot 2.3 at 90 deg: Z1(-15.7,-6.8) Z1(-15.7,0) Z1(0,0) Z1(0,-6.8)
  Keep-Out Layer board cut-out: -14.6,-0.2 -1.1,-0.2 -1.1,-12.15 -14.6,-12.15
  Mechanical 1 keep-out lines w0.127: -1.1,-12.15 -1.1,-0.2 -14.6,-0.2 -14.6,-12.15 -1.1,-12.15
  silkscreen extent -15.16,-12.15 -0.53,3.72, body extent -15.85,-12.15 0.15,3.72, height 3.71
693071020811 [mm] "Micro SD Card Connector Push & Push - with Card Detection - 8 Pins"
  rect 0.7x1.9 smd: 1(2.25,7.75) 2(1.15,7.75) 3(0.05,7.75) 4(-1.05,7.75) 5(-2.15,7.75) 6(-3.25,7.75) 7(-4.35,7.75) 8(-5.45,7.75) 9(-6.55,7.75)
  rect 1.7x1.8 smd: 10(-8.1,6.7) 11(7.4,6.7)
  rect 1.4x2.6 smd: 12(-7.85,-2.9) 13(7.85,-2.9)
  round 0.9 hole 0.9 unplated: MH1(-4.95,-3.3)
  oval 1.7x0.9 hole 0.9 slot 1.7 at 0 deg unplated: MH2(3.05,-3.3)
  silkscreen extent -7.35,-7.25 7.35,7.25, body extent -8.2,-7.3 8.2,7.73, height 1.85
744373560068 [mm] "Precision Wire Wound Inductor, 2-Leads, Body 9,70x8,50mm, IPC High Density"
  rect 2.52x5.33 smd: 1(-3.62,0) 2(3.62,0)
  silkscreen extent -5.1,-4.25 5.1,4.25, body extent -4.95,-4.25 4.95,4.25, height 3.1
ADP1752_1753/ADP1740_1741 [mm] "16-Lead Lead Frame Chip Scale Package [LFCSP_WQ]  4 mm × 4 mm Body, Very Very Thin Quad  (CP-16-23)"
  rect 0.6x0.3 smd: 1(-1.675,0.975) 2(-1.675,0.325) 3(-1.675,-0.325) 4(-1.675,-0.975) 9(1.675,-0.975) 10(1.675,-0.325) 11(1.675,0.325) 12(1.675,0.975)
  rect 0.3x0.6 smd: 5(-0.975,-1.675) 6(-0.325,-1.675) 7(0.325,-1.675) 8(0.975,-1.675) 13(0.975,1.675) 14(0.325,1.675) 15(-0.325,1.675) 16(-0.975,1.675)
  rect 2.1x2.1 smd: 17(0,0)
  silkscreen extent -2.82,-2.05 2.05,2.05, body extent -2.05,-2.05 2.05,2.05, height 0.8
ADP1850 [mm] "32-Lead Lead Frame Chip Scale Package [LFCSP] 5 mm × 5 mm Body and 0.75 mm Package Height (CP-32-12)"
  rect 0.4x0.25 smd: 1(-2.25,1.75) 2(-2.25,1.25) 3(-2.25,0.75) 4(-2.25,0.25) 5(-2.25,-0.25) 6(-2.25,-0.75) 7(-2.25,-1.25) 8(-2.25,-1.75) 17(2.25,-1.75) 18(2.25,-1.25) 19(2.25,-0.75) 20(2.25,-0.25) 21(2.25,0.25) 22(2.25,0.75) 23(2.25,1.25) 24(2.25,1.75)
  rect 0.25x0.4 smd: 9(-1.75,-2.25) 10(-1.25,-2.25) 11(-0.75,-2.25) 12(-0.25,-2.25) 13(0.25,-2.25) 14(0.75,-2.25) 15(1.25,-2.25) 16(1.75,-2.25) 25(1.75,2.25) 26(1.25,2.25) 27(0.75,2.25) 28(0.25,2.25) 29(-0.25,2.25) 30(-0.75,2.25) 31(-1.25,2.25) 32(-1.75,2.25)
  rect 3.6x3.6 smd paste-3: 33(0,0)
  silkscreen extent -3.27,-2.5 2.5,2.5, body extent -2.5,-2.5 2.5,2.5, height 0.8
BAS40-04-TP [mm] "SOT23, 3-Leads, Body 2,92x2,37mm, Pitch 0,90mm, IPC High Density"
  rect 0.9x0.8 smd: 1(-1,0.95) 2(-1,-0.95) 3(1,0)
  silkscreen extent -1.12,-1.5 0.7,1.97, body extent -1.32,-1.52 1.32,1.52, height 1.12
BAT54T1G [mm] "SOD-123  CASE 425-04"
  rect 0.91x1.22 smd: 1(-1.635,0) 2(1.635,0)
  silkscreen extent -2.04,0.86 -1.94,0.96, body extent -1.86,-0.9 1.86,0.9, height 1.35
Battery [mm]
  rect 0.5x1.8 smd: 1(1,0) 2(-1,0)
  Keep-Out Layer circle w0.254: c0,6.858 r4.906
  silkscreen extent -4.86,-2.5 4.91,11.73
BSC030N03LS [mm] "PG-TDSON-8-1"
  rect 0.85x0.6 smd: 1(-2.9,1.905) 2(-2.9,0.635) 3(-2.9,-0.635) 4(-2.9,-1.905)
  rect 0.8x0.6 smd: 5(2.925,-1.905) 6(2.925,-0.635) 7(2.925,0.635) 8(2.925,1.905)
  rect 3.762x4.41 smd paste-2: 8(0.662,0)
  silkscreen extent -3.78,-2.9 3.32,2.94, body extent -3.32,-2.75 3.32,2.75, height 1.1
BSC080N03LS [mm] "PG-TDSON-8-5"
  rect 0.85x0.6 smd: 1(-2.9,1.905) 2(-2.9,0.635) 3(-2.9,-0.635) 4(-2.9,-1.905)
  rect 0.8x0.6 smd: 5(2.925,-1.905) 6(2.925,-0.635) 7(2.925,0.635) 8(2.925,1.905)
  rect 3.762x4.41 smd paste-2: 8(0.662,0)
  silkscreen extent -3.78,-2.9 3.32,2.94, body extent -3.32,-2.75 3.32,2.75, height 1.1
"CAP 0201/0603 RF" [mm] "Chip Capacitor, 2-Leads, Body 0.60x0.30mm, IPC High Density"
  rect 0.3x0.32 smd: 1(-0.26,0) 2(0.26,0)
  silkscreen extent -0.57,-0.33 0.58,0.33, body extent -0.3,-0.15 0.3,0.15, height 0.3
"CAP 0402/1005 RF" [mm] "Chip Capacitor, 2-Leads, Body 1.02x0.51mm, IPC High Density"
  rect 0.55x0.54 smd: 1(-0.39,0) 2(0.39,0)
  silkscreen extent -0.88,-0.45 0.87,0.45, body extent -0.5,-0.26 0.5,0.26, height 0.52
"CAP 0603/1608 RF" [mm] "Chip Capacitor, 2-Leads, Body 1.60x0.80mm, IPC High Density"
  rect 0.8x0.9 smd: 1(-0.625,0) 2(0.625,0)
  silkscreen extent -1.2,-0.62 1.2,0.62, body extent -0.8,-0.41 0.8,0.41, height 0.82
"CAP 0805/2012 RF" [mm] "Chip Capacitor, 2-Leads, Body 2.00x1.20mm, IPC High Density"
  rect 1.1x1.3 smd: 1(-0.7,0) 2(0.7,0)
  silkscreen extent -1.43,-0.82 1.43,0.82, body extent -1,-0.64 1,0.64, height 1.26
"CAP 1206/3216" [mm] "Chip Capacitor, 2-Leads, Body 3.25x1.60mm, IPC Medium Density"
  rect 1.3x1.8 smd: 1(-1.45,0) 2(1.45,0)
  silkscreen extent -2.38,-1.13 2.38,1.13, body extent -1.6,-0.81 1.6,0.81, height 1.62
"CAP 1206/3216 - 0.8MM" [mm] "Chip Capacitor, 2-Leads, Body 3.25x1.60mm, IPC Medium Density"
  rect 1.3x1.8 smd: 1(-1.45,0) 2(1.45,0)
  silkscreen extent -2.37,-1.13 2.38,1.13, body extent -1.6,-0.8 1.6,0.8, height 0.8
"CAP 1210/3225 - 1MM" [mm] "Chip Capacitor, 2-Leads, Body 3.20x2.50mm, IPC Medium Density"
  rect 1.3x2.7 smd: 1(-1.4,0) 2(1.4,0)
  silkscreen extent -2.38,-1.62 2.38,1.62, body extent -1.6,-1.25 1.6,1.25, height 1
"CAP POL 2917/7343" [mm] "Molded Capacitor, 2-Leads, Body 7.30x4.30mm, IPC Medium Density"
  rect 2.55x2.45 smd: 1(-3.025,0) 2(3.025,0)
  silkscreen extent -4.57,-2.3 3.8,2.3, body extent -3.65,-2.15 3.65,2.15, height 4.1
CAPC3326X17L [mm] "Chip Capacitor, 2-Leads, Body 3,30x2,60mm, IPC High Density"
  rect 0.95x2.6 smd: 1(-1.4,0) 2(1.4,0)
  silkscreen extent -0.2,-1.2 0.2,1.2, body extent -1.85,-1.45 1.85,1.45, height 1.7
"CASE 457" [mil] "CASE 457-04, MBRM140T1G"
  rect 105.12x100 smd: 1(-65.06,0)
  rect 30x50 smd: 2(27.5,0)
  silkscreen extent -126,-61 -122,-57, body extent -118,-52 27,53, height 43
CDCM1802RGTT [mm] "PQFN, 16-Leads, Body 3,00x3,00mm, Pitch 0,50mm, Thermal Pad 1,45x1,45mm, IPC High Density"
  rect 0.6x0.24 smd: 1(-1.4,0.75) 2(-1.4,0.25) 3(-1.4,-0.25) 4(-1.4,-0.75) 9(1.4,-0.75) 10(1.4,-0.25) 11(1.4,0.25) 12(1.4,0.75)
  rect 0.24x0.6 smd: 5(-0.75,-1.4) 6(-0.25,-1.4) 7(0.25,-1.4) 8(0.75,-1.4) 13(0.75,1.4) 14(0.25,1.4) 15(-0.25,1.4) 16(-0.75,1.4)
  rect 1.45x1.45 smd paste-0.11: 17(0,0)
  silkscreen extent -2.32,-1.55 1.55,1.55, body extent -1.55,-1.55 1.55,1.55, height 1
CDRH4D28NP [mm] "Precision Wire Wound Inductor, 2-Leads, Body 4,70x4,70mm, IPC High Density"
  rect 1.9x5.3 smd: 1(-1.7,0) 2(1.7,0)
  body extent -2.45,-2.35 2.45,2.35, height 3.1
CDRH5D28 [mm] "CDRH5D28 , Precision Wire Wound Inductor, 2-Leads, Body 6,00x6,00mm, IPC High Density"
  rect 2.15x6.3 smd: 1(-2.075,0) 2(2.075,0)
  silkscreen extent -0.45,-3 0.45,3, body extent -3.1,-3.15 3.1,3.15, height 3.1
Crystal [mm]
  round 1.2 hole 0.6: 1(0,0) 2(4.88,0)
  silkscreen extent -3.81,-1.91 8.69,1.91
CVCO55CW [mm]
  rect 1.32x1.32 smd: 1(0,9.779) 2(0,7.239) 3(0,4.699) 4(0,2.159) 5(2.667,0) 6(5.207,0) 7(7.747,0) 8(10.287,0) 9(12.7,3.048) 10(12.7,5.588) 11(12.7,8.128) 12(12.7,10.668) 13(10.541,12.7) 14(8.001,12.7) 15(5.461,12.7) 16(2.921,12.7)
  silkscreen extent -1.95,0 12.7,12.7
DAC1220 [mm]
  rect 1.6x0.41 smd: 1(-2.667,2.235) 2(-2.667,1.6) 3(-2.667,0.965) 4(-2.667,0.33) 5(-2.667,-0.305) 6(-2.667,-0.94) 7(-2.667,-1.575) 8(-2.667,-2.21) 9(2.667,-2.21) 10(2.667,-1.575) 11(2.667,-0.94) 12(2.667,-0.305) 13(2.667,0.33) 14(2.667,0.965) 15(2.667,1.6) 16(2.667,2.235)
  silkscreen extent -1.55,-2.49 1.55,2.49
"DF005S2 - DF10S2" [mm] "4-LEAD, SDIP, 6.5 MM WIDE"
  rect 1.5x1.3 smd: 1(-4.45,2.55) 2(-4.45,-2.55) 3(4.45,-2.55) 4(4.45,2.55)
  silkscreen extent -4.57,-4.25 2.85,4.25, body extent -4.92,-4.25 4.92,4.25, height 2.6
DFLS1100 [mm] "Molded Diode, 2-Leads, Body 2,80x1,78mm, IPC High Density"
  rect 1.05x1.5 smd: 1(-0.85,0)
  rect 2.4x1.5 smd: 2(1.524,0)
  silkscreen extent -0.81,-1.02 1.27,1.07, body extent -1.02,-0.96 2.42,0.96, height 1
DP83867E [mm] "VQFN, 48-Leads, Body 7,00x7,00mm, Pitch 0,50mm, Thermal Pad 4,10x4,10mm, IPC High Density"
  oval 0.6x0.24 smd: 1(-3.4,2.75) 2(-3.4,2.25) 3(-3.4,1.75) 4(-3.4,1.25) 5(-3.4,0.75) 6(-3.4,0.25) 7(-3.4,-0.25) 8(-3.4,-0.75) 9(-3.4,-1.25) 10(-3.4,-1.75) 11(-3.4,-2.25) 12(-3.4,-2.75) 25(3.4,-2.75) 26(3.4,-2.25) 27(3.4,-1.75) 28(3.4,-1.25) 29(3.4,-0.75) 30(3.4,-0.25) 31(3.4,0.25) 32(3.4,0.75) 33(3.4,1.25) 34(3.4,1.75) 35(3.4,2.25) 36(3.4,2.75)
  oval 0.24x0.6 smd: 13(-2.75,-3.4) 14(-2.25,-3.4) 15(-1.75,-3.4) 16(-1.25,-3.4) 17(-0.75,-3.4) 18(-0.25,-3.4) 19(0.25,-3.4) 20(0.75,-3.4) 21(1.25,-3.4) 22(1.75,-3.4) 23(2.25,-3.4) 24(2.75,-3.4) 37(2.75,3.4) 38(2.25,3.4) 39(1.75,3.4) 40(1.25,3.4) 41(0.75,3.4) 42(0.25,3.4) 43(-0.25,3.4) 44(-0.75,3.4) 45(-1.25,3.4) 46(-1.75,3.4) 47(-2.25,3.4) 48(-2.75,3.4)
  rect 4.1x4.1 smd paste-2.5: 49(0,0)
  silkscreen extent -4.35,-3.57 3.57,3.57, body extent -3.58,-3.57 3.57,3.57, height 1
ECS-120-8-33-RWY-TR [mm] "Ceramic package 4-Leads, Body 2,50x3,20mm, Pitch 1,80mm, IPC High Density"
  rect 1.3x1.1 smd: 1(-1.15,-0.9) 2(1.15,-0.9) 3(1.15,0.9) 4(-1.15,0.9)
  silkscreen extent -2.1,-1.55 -2,-1.45, body extent -1.6,-1.25 1.6,1.25, height 0.8
ESDCAN02-2BWY [mm] "SOT23, 3-Leads, Body 2,00x2,10mm, Pitch 0,65mm, IPC High Density"
  rect 0.7x0.42 smd: 1(-1,0.65) 2(-1,-0.65) 3(1,0)
  silkscreen extent -1.12,-1.1 0.67,1.53, body extent -1.3,-1.1 1.3,1.1, height 1.1
FA-23825.0000MB-C3 [mm] "3.2 x 2.5 x 0.7 mm -- FA-238V / FA-238"
  rect 0.8x0.9 smd: 1(-0.75,1.05) 2(-0.75,-1.05) 3(0.75,-1.05) 4(0.75,1.05)
  silkscreen extent -1.81,1.66 -1.71,1.76, body extent -1.25,-1.6 1.25,1.6, height 0.7
FB0603 [mm] "Chip Inductor, 2-Leads, Body 1,60x0,80mm, IPC High Density"
  rect 0.6x0.85 smd: 1(-0.7,0) 2(0.7,0)
  silkscreen extent -0.05,-0.3 0.05,0.3, body extent -0.8,-0.4 0.8,0.4, height 0.8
